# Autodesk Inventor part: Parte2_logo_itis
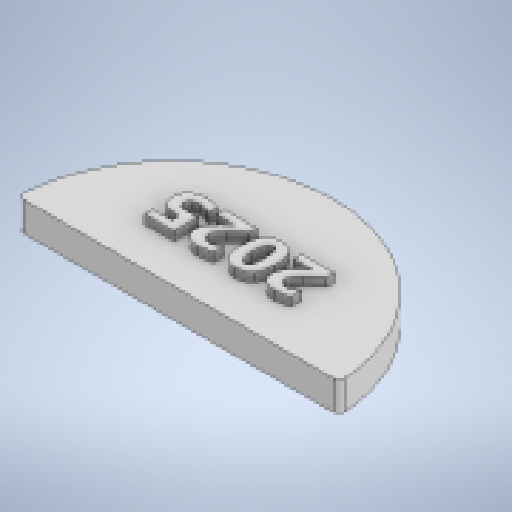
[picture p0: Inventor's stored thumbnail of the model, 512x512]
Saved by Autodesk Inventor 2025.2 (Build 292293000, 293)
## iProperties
Created: 2025-03
Part Number: Parte2_logo_itis
Material: Generico
Document SubType Name: Modeling
Designer: 18907419
Density: 1 g/cm^3
Appearance: Default
Author: 18907419
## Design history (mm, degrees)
sketch "Schizzo1"
  geometry: L1 (0, 0)-(198.619, 0); L2 (198.619, 0)-(198.619, -200); L3 (198.619, -200)-(0, -200); L4 (0, -200)-(0, 0); 1 other entity
  constraints: 2 other
  dimensions: "d1" = 200 distance of L3.end L1.start
  node "Immagine1"
sketch "Schizzo2" dims "d13" = 110
  geometry: L1 (105.821, -199.217)-(91.821, -199.217); L2 (91.821, -199.217)-(89.861, -182.291); L3 (98.821, -199.217)-(98.821, -182.907); L4 (105.821, -199.217)-(107.782, -182.291); L5 (143.188, -189.466)-(130.253, -194.824); L6 (130.253, -194.824)-(121.965, -179.936); L7 (136.721, -192.145)-(130.479, -177.077); L8 (143.188, -189.466)-(138.521, -173.078); L9 (173.978, -166.158)-(164.079, -176.058); L10 (164.079, -176.058)-(150.724, -165.475); L11 (169.028, -171.108)-(157.495, -159.575); L12 (173.978, -166.158)-(163.395, -152.804); L13 (193.505, -132.842)-(188.148, -145.776); L14 (188.148, -145.776)-(171.76, -141.109); L15 (190.826, -139.309)-(175.758, -133.067); L16 (193.505, -132.842)-(178.617, -124.553); L17 (198.796, -94.588)-(198.796, -108.588); L18 (198.796, -108.588)-(181.87, -110.548); L19 (198.796, -101.588)-(182.486, -101.588); L20 (198.796, -94.588)-(181.87, -92.628); L21 (189.045, -57.222)-(194.403, -70.156); L22 (194.403, -70.156)-(179.515, -78.445); L23 (191.724, -63.689)-(176.655, -69.931); L24 (189.045, -57.222)-(172.657, -61.888); L25 (165.737, -26.431)-(175.637, -36.331); L26 (175.637, -36.331)-(165.054, -49.686); L27 (170.687, -31.381)-(159.154, -42.914); L28 (165.737, -26.431)-(152.382, -37.014); L29 (132.42, -6.904)-(145.355, -12.262); L30 (145.355, -12.262)-(140.688, -28.65); L31 (138.888, -9.583)-(132.646, -24.652); L32 (132.42, -6.904)-(124.132, -21.792); L33 (94.167, -1.614)-(108.167, -1.614); L34 (108.167, -1.614)-(110.127, -18.54); L35 (101.167, -1.614)-(101.167, -17.924); L36 (94.167, -1.614)-(92.207, -18.54); L37 (56.801, -11.364)-(69.735, -6.007); L38 (69.735, -6.007)-(78.023, -20.895); L39 (63.268, -8.686)-(69.51, -23.754); L40 (56.801, -11.364)-(61.467, -27.753); L41 (26.01, -34.672)-(35.91, -24.773); L42 (35.91, -24.773)-(49.265, -35.356); L43 (30.96, -29.723)-(42.493, -41.256); L44 (26.01, -34.672)-(36.593, -48.027); L45 (6.483, -67.989)-(11.841, -55.055); L46 (11.841, -55.055)-(28.229, -59.721); L47 (9.162, -61.522)-(24.231, -67.764); L48 (6.483, -67.989)-(21.371, -76.278); L49 (1.192, -106.243)-(1.192, -92.243); L50 (1.192, -92.243)-(18.119, -90.283); L51 (1.192, -99.243)-(17.503, -99.243); L52 (1.192, -106.243)-(18.119, -108.203); L53 (10.943, -143.609)-(5.586, -130.675); L54 (5.586, -130.675)-(20.474, -122.386); L55 (8.264, -137.142)-(23.333, -130.9); L56 (10.943, -143.609)-(27.331, -138.942); L57 (34.251, -174.399)-(24.352, -164.5); L58 (24.352, -164.5)-(34.935, -151.145); L59 (29.301, -169.45)-(40.835, -157.917); L60 (34.251, -174.399)-(47.606, -163.816); L61 (67.568, -193.926)-(54.634, -188.569); L62 (54.634, -188.569)-(59.3, -172.181); L63 (61.101, -191.248)-(67.343, -176.179); L64 (67.568, -193.926)-(75.856, -179.038)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; A1 r 82.5 centre (99.994, -100.415) between (89.861, -182.291) and (98.821, -182.907); A2 r 80 centre (81.89, -116.945) between (124.568, -184.611) and (153.002, -80.297); A3 r 85 centre (79.253, -82.612) between (32.823, -153.81) and (129.534, -151.145); A4 r 61.843 centre (94.454, -100.214) between (129.534, -151.145) and (153.002, -80.297); 10 further points
  constraints: 134 end point, 9 point on circle, 4 centre point, 4 horizontal, 2 point on line, 1 coincident, 1 midpoint, 1 parallel, 1 symmetric about line, 1 vertical, 164 other
  dimensions: "d2" = 165 diameter of A1; "d3" = 14 distance of L1.start L1.end; "d6" = 360 deg dimension on A1.centre L1.start (derived); "d8" = 80 radius of A2; "d14" = 2 distance between parallel lines of L65 L66
extrude "Estrusione2" new body sketch "Schizzo2" distance "d15" = 10; taper "d16" = 0 deg
fillet "Raccordo1" dims "d17" = 2
sketch "Schizzo3"
  geometry: L1 (-73.638, 115.455)-(-133.482, 115.455); L2 (-133.482, 115.455)-(-133.482, 134.229); L3 (-133.482, 134.229)-(-73.638, 134.229); L4 (-73.638, 134.229)-(-73.638, 115.455); 1 further point
  constraints: 2 other
extrude "Estrusione3" join sketch "Schizzo3" distance "d18" = 3; taper "d19" = 0 deg
node "Solido2"
node "Schizzo - Serie circolare1" dims "d6" = 360 deg (derived)
